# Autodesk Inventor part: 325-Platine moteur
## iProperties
Author: Philippe
Created: 2001-12
Part Number: 325-Platine moteur
Material: Par défaut
Document SubType Name: Modélisation
Designer: Philippe
Control State: 0
Master: False
Checked Out: False
PropertySet Name: Design Tracking Control
Shininess: 20.0
Angle Display Precision: 2
Document Length Units: 11269
Document Angle Units: 11283
Document Time Units: 11279
Document Mass Units: 11290
Document Length Units Precision: 3
Document Angle Units Precision: 2
Compacted: False
PropertySet Name: _Private Model Information
Density: 0.0
Volumn: 0.0
Area: 0.0
PropertySet Name: Model Information
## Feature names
1. Extrusion1
2. Chanfrein1 [Chamfer]
3. Perçage2 [Hole]
